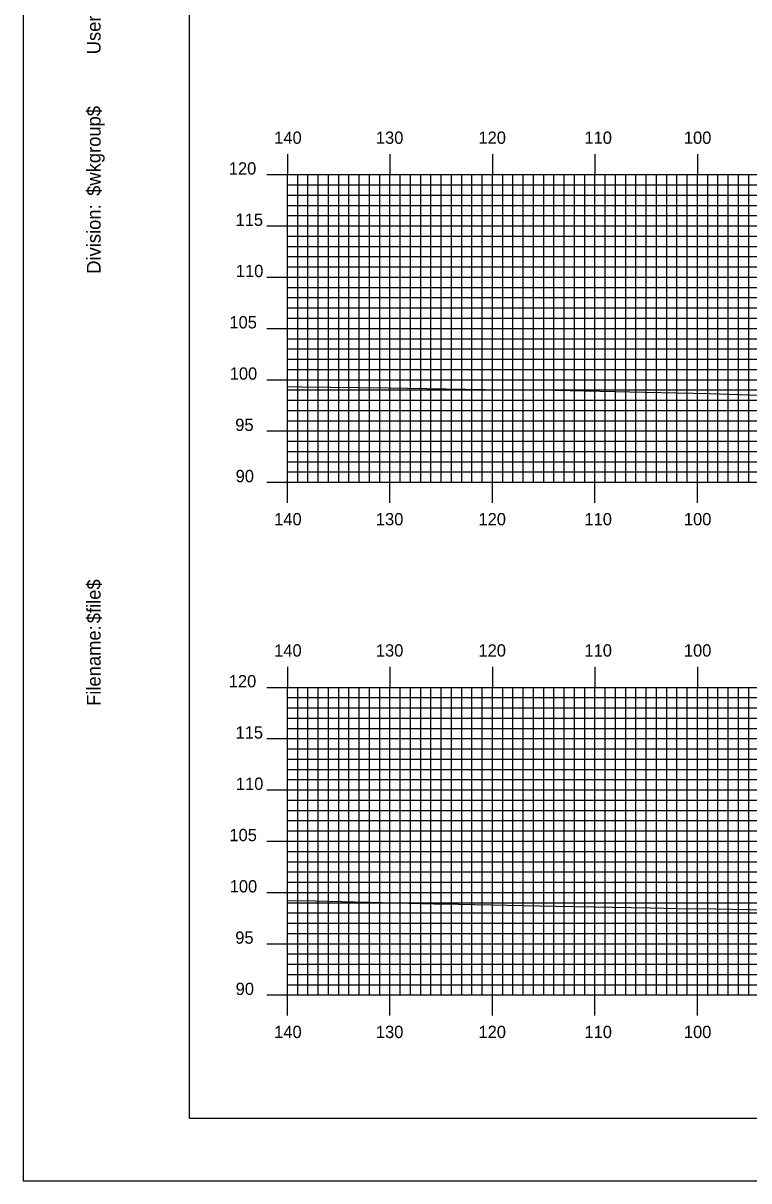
# Model space of a CAD drawing. Extents: x 1786976 to 1787319, y 442591 to 442811.
# Drawn here: x 1786975.8 to 1787046.6, y 442590.5 to 442703.4 of the extents above; entities that cross this region are included whole.
import ezdxf

# ---------------------------------------------------------------- set-up
doc = ezdxf.new("R2010")
doc.units = 0
for name, color, linetype in [('BORDER', 7, 'Continuous'), ('H_V ANNOTATION', 7, 'Continuous'), ('MAJOR', 7, 'Continuous'), ('MINOR', 7, 'Continuous'), ('PLOT BOUNDARY', 7, 'Continuous'), ('S_Roadway_Centerline', 7, 'Continuous')]:
    doc.layers.add(name, color=color, linetype=linetype)

msp = doc.modelspace()

# ---------------------------------------------------------------- linework, layer by layer
at = {"layer": 'BORDER'}
msp.add_lwpolyline([(1786991.99, 442596.67), (1787311.99, 442596.67), (1787311.99, 442806.67), (1786991.99, 442806.67)], close=True, dxfattribs=at)
at = {"layer": 'MAJOR'}
for p, q in [((1787001.59, 442690.67), (1787001.59, 442688.67)), ((1787011.59, 442690.67), (1787011.59, 442688.67)), ((1787021.59, 442690.67), (1787021.59, 442688.67)), ((1787031.59, 442690.67), (1787031.59, 442688.67)), ((1787041.59, 442690.67), (1787041.59, 442688.67)), ((1786999.59, 442688.67), (1787001.59, 442688.67)), ((1787001.59, 442688.67), (1787281.59, 442688.67)), ((1787001.59, 442658.67), (1787001.59, 442688.67)), ((1787001.59, 442658.67), (1787001.59, 442688.67)), ((1787001.59, 442688.67), (1787281.59, 442688.67)), ((1787011.59, 442658.67), (1787011.59, 442688.67)), ((1787021.59, 442658.67), (1787021.59, 442688.67)), ((1787031.59, 442658.67), (1787031.59, 442688.67)), ((1787041.59, 442658.67), (1787041.59, 442688.67)), ((1786999.59, 442683.67), (1787001.59, 442683.67)), ((1787001.59, 442683.67), (1787281.59, 442683.67)), ((1786999.59, 442678.67), (1787001.59, 442678.67)), ((1787001.59, 442678.67), (1787281.59, 442678.67)), ((1786999.59, 442673.67), (1787001.59, 442673.67)), ((1787001.59, 442673.67), (1787281.59, 442673.67)), ((1786999.59, 442668.67), (1787001.59, 442668.67)), ((1787001.59, 442668.67), (1787281.59, 442668.67)), ((1786999.59, 442663.67), (1787001.59, 442663.67)), ((1787001.59, 442663.67), (1787281.59, 442663.67)), ((1786999.59, 442658.67), (1787001.59, 442658.67)), ((1787001.59, 442658.67), (1787281.59, 442658.67)), ((1787001.59, 442658.67), (1787281.59, 442658.67)), ((1787001.59, 442656.66), (1787001.59, 442658.67)), ((1787011.59, 442656.66), (1787011.59, 442658.67)), ((1787021.59, 442656.66), (1787021.59, 442658.67)), ((1787031.59, 442656.66), (1787031.59, 442658.67)), ((1787041.59, 442656.66), (1787041.59, 442658.67)), ((1787001.59, 442640.67), (1787001.59, 442638.67)), ((1787011.59, 442640.67), (1787011.59, 442638.67)), ((1787021.59, 442640.67), (1787021.59, 442638.67)), ((1787031.59, 442640.67), (1787031.59, 442638.67)), ((1787041.59, 442640.67), (1787041.59, 442638.67)), ((1786999.59, 442638.67), (1787001.59, 442638.67)), ((1787001.59, 442638.67), (1787281.59, 442638.67)), ((1787001.59, 442608.67), (1787001.59, 442638.67)), ((1787001.59, 442608.67), (1787001.59, 442638.67)), ((1787001.59, 442638.67), (1787281.59, 442638.67)), ((1787011.59, 442608.67), (1787011.59, 442638.67)), ((1787021.59, 442608.67), (1787021.59, 442638.67)), ((1787031.59, 442608.67), (1787031.59, 442638.67)), ((1787041.59, 442608.67), (1787041.59, 442638.67)), ((1786999.59, 442633.67), (1787001.59, 442633.67)), ((1787001.59, 442633.67), (1787281.59, 442633.67)), ((1786999.59, 442628.67), (1787001.59, 442628.67)), ((1787001.59, 442628.67), (1787281.59, 442628.67)), ((1786999.59, 442623.67), (1787001.59, 442623.67)), ((1787001.59, 442623.67), (1787281.59, 442623.67)), ((1786999.59, 442618.67), (1787001.59, 442618.67)), ((1787001.59, 442618.67), (1787281.59, 442618.67)), ((1786999.59, 442613.67), (1787001.59, 442613.67)), ((1787001.59, 442613.67), (1787281.59, 442613.67)), ((1786999.59, 442608.67), (1787001.59, 442608.67)), ((1787001.59, 442608.67), (1787281.59, 442608.67)), ((1787001.59, 442608.67), (1787281.59, 442608.67)), ((1787001.59, 442606.66), (1787001.59, 442608.67)), ((1787011.59, 442606.66), (1787011.59, 442608.67)), ((1787021.59, 442606.66), (1787021.59, 442608.67)), ((1787031.59, 442606.66), (1787031.59, 442608.67)), ((1787041.59, 442606.66), (1787041.59, 442608.67))]:
    msp.add_line(p, q, dxfattribs=at)
at = {"layer": 'MINOR'}
for p, q in [((1787002.59, 442658.67), (1787002.59, 442688.67)), ((1787003.59, 442658.67), (1787003.59, 442688.67)), ((1787004.59, 442658.67), (1787004.59, 442688.67)), ((1787005.59, 442658.67), (1787005.59, 442688.67)), ((1787006.59, 442658.67), (1787006.59, 442688.67)), ((1787007.59, 442658.67), (1787007.59, 442688.67)), ((1787008.59, 442658.67), (1787008.59, 442688.67)), ((1787009.59, 442658.67), (1787009.59, 442688.67)), ((1787010.59, 442658.67), (1787010.59, 442688.67)), ((1787012.59, 442658.67), (1787012.59, 442688.67)), ((1787013.59, 442658.67), (1787013.59, 442688.67)), ((1787014.59, 442658.67), (1787014.59, 442688.67)), ((1787015.59, 442658.67), (1787015.59, 442688.67)), ((1787016.59, 442658.67), (1787016.59, 442688.67)), ((1787017.59, 442658.67), (1787017.59, 442688.67)), ((1787018.59, 442658.67), (1787018.59, 442688.67)), ((1787019.59, 442658.67), (1787019.59, 442688.67)), ((1787020.59, 442658.67), (1787020.59, 442688.67)), ((1787022.59, 442658.67), (1787022.59, 442688.67)), ((1787023.59, 442658.67), (1787023.59, 442688.67)), ((1787024.59, 442658.67), (1787024.59, 442688.67)), ((1787025.59, 442658.67), (1787025.59, 442688.67)), ((1787026.59, 442658.67), (1787026.59, 442688.67)), ((1787027.59, 442658.67), (1787027.59, 442688.67)), ((1787028.59, 442658.67), (1787028.59, 442688.67)), ((1787029.59, 442658.67), (1787029.59, 442688.67)), ((1787030.59, 442658.67), (1787030.59, 442688.67)), ((1787032.59, 442658.67), (1787032.59, 442688.67)), ((1787033.59, 442658.67), (1787033.59, 442688.67)), ((1787034.59, 442658.67), (1787034.59, 442688.67)), ((1787035.59, 442658.67), (1787035.59, 442688.67)), ((1787036.59, 442658.67), (1787036.59, 442688.67)), ((1787037.59, 442658.67), (1787037.59, 442688.67)), ((1787038.59, 442658.67), (1787038.59, 442688.67)), ((1787039.59, 442658.67), (1787039.59, 442688.67)), ((1787040.59, 442658.67), (1787040.59, 442688.67)), ((1787042.59, 442658.67), (1787042.59, 442688.67)), ((1787043.59, 442658.67), (1787043.59, 442688.67)), ((1787044.59, 442658.67), (1787044.59, 442688.67)), ((1787045.59, 442658.67), (1787045.59, 442688.67)), ((1787046.59, 442658.67), (1787046.59, 442688.67)), ((1787001.59, 442687.67), (1787281.59, 442687.67)), ((1787001.59, 442687.67), (1787003.6, 442687.67)), ((1787001.59, 442686.67), (1787281.59, 442686.67)), ((1787001.59, 442686.67), (1787003.6, 442686.67)), ((1787001.59, 442685.67), (1787281.59, 442685.67)), ((1787001.59, 442685.67), (1787003.6, 442685.67)), ((1787001.59, 442684.67), (1787281.59, 442684.67)), ((1787001.59, 442684.67), (1787003.6, 442684.67)), ((1787001.59, 442682.67), (1787281.59, 442682.67)), ((1787001.59, 442682.67), (1787003.6, 442682.67)), ((1787001.59, 442681.67), (1787281.59, 442681.67)), ((1787001.59, 442681.67), (1787003.6, 442681.67)), ((1787001.59, 442680.67), (1787281.59, 442680.67)), ((1787001.59, 442680.67), (1787003.6, 442680.67)), ((1787001.59, 442679.67), (1787281.59, 442679.67)), ((1787001.59, 442679.67), (1787003.6, 442679.67)), ((1787001.59, 442677.67), (1787281.59, 442677.67)), ((1787001.59, 442677.67), (1787003.6, 442677.67)), ((1787001.59, 442676.67), (1787281.59, 442676.67)), ((1787001.59, 442676.67), (1787003.6, 442676.67)), ((1787001.59, 442675.67), (1787281.59, 442675.67)), ((1787001.59, 442675.67), (1787003.6, 442675.67)), ((1787001.59, 442674.67), (1787281.59, 442674.67)), ((1787001.59, 442674.67), (1787003.6, 442674.67)), ((1787001.59, 442672.67), (1787281.59, 442672.67)), ((1787001.59, 442672.67), (1787003.6, 442672.67)), ((1787001.59, 442671.67), (1787281.59, 442671.67)), ((1787001.59, 442671.67), (1787003.6, 442671.67)), ((1787001.59, 442670.67), (1787281.59, 442670.67)), ((1787001.59, 442670.67), (1787003.6, 442670.67)), ((1787001.59, 442669.67), (1787281.59, 442669.67)), ((1787001.59, 442669.67), (1787003.6, 442669.67)), ((1787001.59, 442667.67), (1787281.59, 442667.67)), ((1787001.59, 442667.67), (1787003.6, 442667.67)), ((1787001.59, 442666.67), (1787281.59, 442666.67)), ((1787001.59, 442666.67), (1787003.6, 442666.67)), ((1787001.59, 442665.67), (1787281.59, 442665.67)), ((1787001.59, 442665.67), (1787003.6, 442665.67)), ((1787001.59, 442664.67), (1787281.59, 442664.67)), ((1787001.59, 442664.67), (1787003.6, 442664.67)), ((1787001.59, 442662.67), (1787281.59, 442662.67)), ((1787001.59, 442662.67), (1787003.6, 442662.67)), ((1787001.59, 442661.67), (1787281.59, 442661.67)), ((1787001.59, 442661.67), (1787003.6, 442661.67)), ((1787001.59, 442660.67), (1787281.59, 442660.67)), ((1787001.59, 442660.67), (1787003.6, 442660.67)), ((1787001.59, 442659.67), (1787281.59, 442659.67)), ((1787001.59, 442659.67), (1787003.6, 442659.67)), ((1787002.59, 442608.67), (1787002.59, 442638.67)), ((1787003.59, 442608.67), (1787003.59, 442638.67)), ((1787004.59, 442608.67), (1787004.59, 442638.67)), ((1787005.59, 442608.67), (1787005.59, 442638.67)), ((1787006.59, 442608.67), (1787006.59, 442638.67)), ((1787007.59, 442608.67), (1787007.59, 442638.67)), ((1787008.59, 442608.67), (1787008.59, 442638.67)), ((1787009.59, 442608.67), (1787009.59, 442638.67)), ((1787010.59, 442608.67), (1787010.59, 442638.67)), ((1787012.59, 442608.67), (1787012.59, 442638.67)), ((1787013.59, 442608.67), (1787013.59, 442638.67)), ((1787014.59, 442608.67), (1787014.59, 442638.67)), ((1787015.59, 442608.67), (1787015.59, 442638.67)), ((1787016.59, 442608.67), (1787016.59, 442638.67)), ((1787017.59, 442608.67), (1787017.59, 442638.67)), ((1787018.59, 442608.67), (1787018.59, 442638.67)), ((1787019.59, 442608.67), (1787019.59, 442638.67)), ((1787020.59, 442608.67), (1787020.59, 442638.67)), ((1787022.59, 442608.67), (1787022.59, 442638.67)), ((1787023.59, 442608.67), (1787023.59, 442638.67)), ((1787024.59, 442608.67), (1787024.59, 442638.67)), ((1787025.59, 442608.67), (1787025.59, 442638.67)), ((1787026.59, 442608.67), (1787026.59, 442638.67)), ((1787027.59, 442608.67), (1787027.59, 442638.67)), ((1787028.59, 442608.67), (1787028.59, 442638.67)), ((1787029.59, 442608.67), (1787029.59, 442638.67)), ((1787030.59, 442608.67), (1787030.59, 442638.67)), ((1787032.59, 442608.67), (1787032.59, 442638.67)), ((1787033.59, 442608.67), (1787033.59, 442638.67)), ((1787034.59, 442608.67), (1787034.59, 442638.67)), ((1787035.59, 442608.67), (1787035.59, 442638.67)), ((1787036.59, 442608.67), (1787036.59, 442638.67)), ((1787037.59, 442608.67), (1787037.59, 442638.67)), ((1787038.59, 442608.67), (1787038.59, 442638.67)), ((1787039.59, 442608.67), (1787039.59, 442638.67)), ((1787040.59, 442608.67), (1787040.59, 442638.67)), ((1787042.59, 442608.67), (1787042.59, 442638.67)), ((1787043.59, 442608.67), (1787043.59, 442638.67)), ((1787044.59, 442608.67), (1787044.59, 442638.67)), ((1787045.59, 442608.67), (1787045.59, 442638.67)), ((1787046.59, 442608.67), (1787046.59, 442638.67)), ((1787001.59, 442637.67), (1787281.59, 442637.67)), ((1787001.59, 442637.67), (1787003.6, 442637.67)), ((1787001.59, 442636.67), (1787281.59, 442636.67)), ((1787001.59, 442636.67), (1787003.6, 442636.67)), ((1787001.59, 442635.67), (1787281.59, 442635.67)), ((1787001.59, 442635.67), (1787003.6, 442635.67)), ((1787001.59, 442634.67), (1787281.59, 442634.67)), ((1787001.59, 442634.67), (1787003.6, 442634.67)), ((1787001.59, 442632.67), (1787281.59, 442632.67)), ((1787001.59, 442632.67), (1787003.6, 442632.67)), ((1787001.59, 442631.67), (1787281.59, 442631.67)), ((1787001.59, 442631.67), (1787003.6, 442631.67)), ((1787001.59, 442630.67), (1787281.59, 442630.67)), ((1787001.59, 442630.67), (1787003.6, 442630.67)), ((1787001.59, 442629.67), (1787281.59, 442629.67)), ((1787001.59, 442629.67), (1787003.6, 442629.67)), ((1787001.59, 442627.67), (1787281.59, 442627.67)), ((1787001.59, 442627.67), (1787003.6, 442627.67)), ((1787001.59, 442626.67), (1787281.59, 442626.67)), ((1787001.59, 442626.67), (1787003.6, 442626.67)), ((1787001.59, 442625.67), (1787281.59, 442625.67)), ((1787001.59, 442625.67), (1787003.6, 442625.67)), ((1787001.59, 442624.67), (1787281.59, 442624.67)), ((1787001.59, 442624.67), (1787003.6, 442624.67)), ((1787001.59, 442622.67), (1787281.59, 442622.67)), ((1787001.59, 442622.67), (1787003.6, 442622.67)), ((1787001.59, 442621.67), (1787281.59, 442621.67)), ((1787001.59, 442621.67), (1787003.6, 442621.67)), ((1787001.59, 442620.67), (1787281.59, 442620.67)), ((1787001.59, 442620.67), (1787003.6, 442620.67)), ((1787001.59, 442619.67), (1787281.59, 442619.67)), ((1787001.59, 442619.67), (1787003.6, 442619.67)), ((1787001.59, 442617.67), (1787281.59, 442617.67)), ((1787001.59, 442617.67), (1787003.6, 442617.67)), ((1787001.59, 442616.67), (1787281.59, 442616.67)), ((1787001.59, 442616.67), (1787003.6, 442616.67)), ((1787001.59, 442615.67), (1787281.59, 442615.67)), ((1787001.59, 442615.67), (1787003.6, 442615.67)), ((1787001.59, 442614.67), (1787281.59, 442614.67)), ((1787001.59, 442614.67), (1787003.6, 442614.67)), ((1787001.59, 442612.67), (1787281.59, 442612.67)), ((1787001.59, 442612.67), (1787003.6, 442612.67)), ((1787001.59, 442611.67), (1787281.59, 442611.67)), ((1787001.59, 442611.67), (1787003.6, 442611.67)), ((1787001.59, 442610.67), (1787281.59, 442610.67)), ((1787001.59, 442610.67), (1787003.6, 442610.67)), ((1787001.59, 442609.67), (1787281.59, 442609.67)), ((1787001.59, 442609.67), (1787003.6, 442609.67))]:
    msp.add_line(p, q, dxfattribs=at)
at = {"layer": 'PLOT BOUNDARY'}
msp.add_lwpolyline([(1786975.8, 442590.55), (1787315.8, 442590.55), (1787315.8, 442810.55), (1786975.8, 442810.55)], close=True, dxfattribs=at)
at = {"layer": 'S_Roadway_Centerline'}
for points in [[(1787001.59, 442668), (1787002.96, 442667.98), (1787011.42, 442667.88), (1787022.78, 442667.68), (1787027.72, 442667.65), (1787036.47, 442667.45), (1787042.77, 442667.31), (1787048.56, 442667.12)], [(1787001.59, 442617.9), (1787004.29, 442617.85), (1787014.73, 442617.6), (1787015.91, 442617.57), (1787016.7, 442617.55), (1787027.79, 442617.34), (1787037.02, 442617.16), (1787039.65, 442617.11), (1787043.32, 442617.07), (1787056.87, 442616.81)]]:
    msp.add_lwpolyline(points, dxfattribs=at)

# ---------------------------------------------------------------- texts
at = {"layer": 'BORDER'}
for s, p in [('Username:', (1786983.36, 442700.4)), ('$wkgroup$', (1786983.36, 442686.6)), ('Division:', (1786983.36, 442679)), ('$file$', (1786983.36, 442644.92)), ('Filename:', (1786983.36, 442636.86))]:
    msp.add_text(s, height=1.339, rotation=90, dxfattribs=at).set_placement(p)
at = {"layer": 'H_V ANNOTATION'}
for s, p in [('140', (1787000.3, 442691.67)), ('130', (1787010.22, 442691.67)), ('120', (1787020.23, 442691.67)), ('110', (1787030.57, 442691.67)), ('100', (1787040.27, 442691.67)), ('120', (1786995.87, 442688.67)), ('115', (1786996.53, 442683.67)), ('110', (1786996.56, 442678.67)), ('105', (1786995.93, 442673.67)), ('100', (1786995.96, 442668.67)), ('95', (1786996.5, 442663.67)), ('90', (1786996.54, 442658.67)), ('140', (1787000.3, 442654.47)), ('130', (1787010.22, 442654.47)), ('120', (1787020.23, 442654.47)), ('110', (1787030.57, 442654.47)), ('100', (1787040.27, 442654.47)), ('140', (1787000.3, 442641.67)), ('130', (1787010.22, 442641.67)), ('120', (1787020.23, 442641.67)), ('110', (1787030.57, 442641.67)), ('100', (1787040.27, 442641.67)), ('120', (1786995.87, 442638.67)), ('115', (1786996.53, 442633.67)), ('110', (1786996.56, 442628.67)), ('105', (1786995.93, 442623.67)), ('100', (1786995.96, 442618.67)), ('95', (1786996.5, 442613.67)), ('90', (1786996.54, 442608.67)), ('140', (1787000.3, 442604.47)), ('130', (1787010.22, 442604.47)), ('120', (1787020.23, 442604.47)), ('110', (1787030.57, 442604.47)), ('100', (1787040.27, 442604.47))]:
    msp.add_text(s, height=1.2, dxfattribs=at).set_placement(p)
at = {"layer": 'MAJOR'}
for p in [(1787001.58, 442658.67), (1787001.58, 442608.67)]:
    msp.add_text('-', height=0.012, dxfattribs=at).set_placement(p)

doc.saveas('drawing.dxf')
